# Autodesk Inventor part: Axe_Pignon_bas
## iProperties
Created: 2008-11
Part Number: Axe_Pignon_bas
Document SubType Name: Modeling
Designer: ETUDIANT
Author: ETUDIANT
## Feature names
1. Révolution1 [Revolution]
2. Perçage1 [Hole]
3. Perçage2 [Hole]
4. Chanfrein1 [Chamfer]
